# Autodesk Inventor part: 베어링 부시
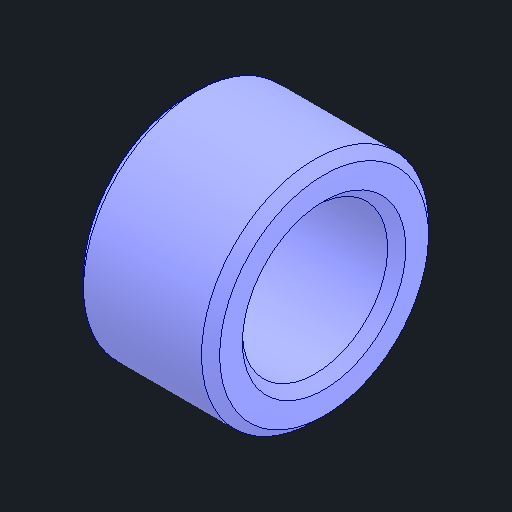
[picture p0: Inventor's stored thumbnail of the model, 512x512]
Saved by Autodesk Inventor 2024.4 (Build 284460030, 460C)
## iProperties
Created: 2026-09
Part Number: 베어링 부시
Material: 강철, 연강
Document SubType Name: Modeling
Designer: user
Density: 7.86 g/cm^3
Appearance: 기본값
Author: jhkim
Sending System: Autodesk Inventor 2027
Preprocessor: ST-DEVELOPER v20.1
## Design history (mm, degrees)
feature "솔리드1"
node "솔리드2"
